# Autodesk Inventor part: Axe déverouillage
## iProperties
Author: Flavien MARTY
Shininess: 60.0
PropertySet Name: _Private Model Information
Created: 2001-10
Part Number: Axe déverouillage
Material: Par défaut
Document SubType Name: Modélisation
Designer: Flavien MARTY
Control State: 0
Master: False
Checked Out: False
PropertySet Name: Design Tracking Control
Density: 0.0
Volumn: 0.0
Area: 0.0
PropertySet Name: Model Information
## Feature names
1. Base1
